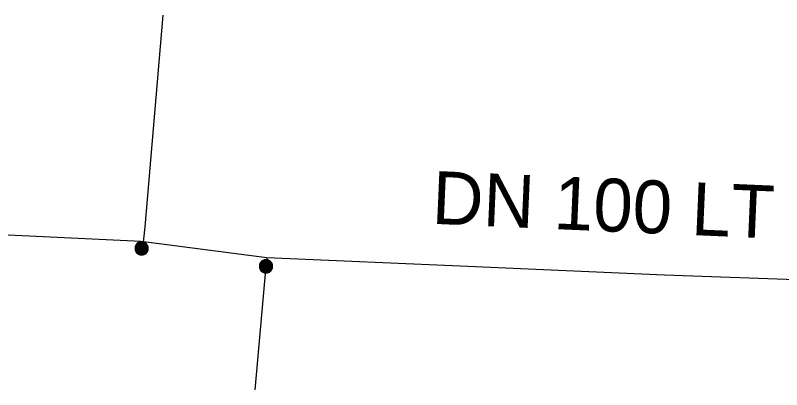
# Model space of a CAD drawing. Extents: x -832382 to -831581, y -1074670 to -1074251.
# Drawn here: x -831799.98 to -831771.02, y -1074605.05 to -1074590.89 of the extents above; entities that cross this region are included whole.
import ezdxf

# ---------------------------------------------------------------- set-up
doc = ezdxf.new("R2010")
doc.units = 0
for name, color, linetype in [('Přípojka vodovodu', 7, 'Continuous'), ('Přípojkový uzávěr', 7, 'Continuous'), ('Roz-řad', 7, 'Continuous'), ('Roz-řad-popis základní', 7, 'Continuous')]:
    doc.layers.add(name, color=color, linetype=linetype)

msp = doc.modelspace()

# ---------------------------------------------------------------- linework, layer by layer
at = {"layer": 'Přípojka vodovodu'}
for points in [[(-831795.23, -1074599.43), (-831795.21, -1074599.7), (-831795.19, -1074599.93), (-831795.08, -1074598.89), (-831794.395, -1074590.887)], [(-831790.48, -1074600.05), (-831790.51, -1074600.38), (-831790.934, -1074605.047)]]:
    msp.add_lwpolyline(points, dxfattribs=at)
at = {"layer": 'Přípojkový uzávěr'}
for points in [[(-831795.21, -1074599.45), (-831795.147, -1074599.45), (-831795.087, -1074599.482), (-831795.028, -1074599.514), (-831794.994, -1074599.575), (-831794.96, -1074599.635), (-831794.96, -1074599.7), (-831794.96, -1074599.765), (-831794.993, -1074599.825), (-831795.026, -1074599.884), (-831795.085, -1074599.917), (-831795.145, -1074599.95), (-831795.21, -1074599.95), (-831795.275, -1074599.95), (-831795.335, -1074599.917), (-831795.394, -1074599.884), (-831795.427, -1074599.825), (-831795.46, -1074599.765), (-831795.46, -1074599.7), (-831795.46, -1074599.635), (-831795.426, -1074599.575), (-831795.393, -1074599.514), (-831795.333, -1074599.482), (-831795.273, -1074599.45), (-831795.21, -1074599.45)], [(-831795.21, -1074599.473), (-831795.267, -1074599.473), (-831795.322, -1074599.503), (-831795.376, -1074599.532), (-831795.406, -1074599.586), (-831795.437, -1074599.641), (-831795.437, -1074599.7), (-831795.437, -1074599.759), (-831795.407, -1074599.813), (-831795.377, -1074599.867), (-831795.323, -1074599.897), (-831795.269, -1074599.927), (-831795.21, -1074599.927), (-831795.151, -1074599.927), (-831795.097, -1074599.897), (-831795.043, -1074599.867), (-831795.013, -1074599.813), (-831794.983, -1074599.759), (-831794.983, -1074599.7), (-831794.983, -1074599.641), (-831795.014, -1074599.586), (-831795.045, -1074599.532), (-831795.099, -1074599.503), (-831795.153, -1074599.473), (-831795.21, -1074599.473)], [(-831795.21, -1074599.491), (-831795.157, -1074599.491), (-831795.107, -1074599.518), (-831795.057, -1074599.544), (-831795.029, -1074599.595), (-831795.001, -1074599.645), (-831795.001, -1074599.7), (-831795.001, -1074599.755), (-831795.028, -1074599.804), (-831795.055, -1074599.854), (-831795.106, -1074599.882), (-831795.156, -1074599.909), (-831795.21, -1074599.909), (-831795.264, -1074599.909), (-831795.314, -1074599.882), (-831795.365, -1074599.854), (-831795.392, -1074599.804), (-831795.419, -1074599.755), (-831795.419, -1074599.7), (-831795.419, -1074599.645), (-831795.391, -1074599.595), (-831795.363, -1074599.544), (-831795.313, -1074599.518), (-831795.263, -1074599.491), (-831795.21, -1074599.491)], [(-831795.21, -1074599.512), (-831795.289, -1074599.512), (-831795.343, -1074599.567), (-831795.397, -1074599.622), (-831795.397, -1074599.7), (-831795.397, -1074599.778), (-831795.343, -1074599.833), (-831795.288, -1074599.887), (-831795.21, -1074599.887), (-831795.132, -1074599.887), (-831795.077, -1074599.833), (-831795.022, -1074599.778), (-831795.022, -1074599.7), (-831795.022, -1074599.622), (-831795.077, -1074599.567), (-831795.132, -1074599.512), (-831795.21, -1074599.512)], [(-831795.21, -1074599.535), (-831795.142, -1074599.535), (-831795.094, -1074599.583), (-831795.046, -1074599.631), (-831795.046, -1074599.7), (-831795.046, -1074599.768), (-831795.094, -1074599.816), (-831795.142, -1074599.864), (-831795.21, -1074599.864), (-831795.279, -1074599.864), (-831795.327, -1074599.816), (-831795.375, -1074599.768), (-831795.375, -1074599.7), (-831795.375, -1074599.631), (-831795.327, -1074599.583), (-831795.279, -1074599.535), (-831795.21, -1074599.535)], [(-831795.21, -1074599.555), (-831795.271, -1074599.555), (-831795.313, -1074599.597), (-831795.355, -1074599.64), (-831795.355, -1074599.7), (-831795.355, -1074599.759), (-831795.313, -1074599.802), (-831795.271, -1074599.844), (-831795.21, -1074599.844), (-831795.151, -1074599.844), (-831795.108, -1074599.802), (-831795.066, -1074599.759), (-831795.066, -1074599.7), (-831795.066, -1074599.64), (-831795.108, -1074599.597), (-831795.15, -1074599.555), (-831795.21, -1074599.555)], [(-831795.21, -1074599.575), (-831795.158, -1074599.575), (-831795.121, -1074599.612), (-831795.085, -1074599.648), (-831795.085, -1074599.7), (-831795.085, -1074599.752), (-831795.122, -1074599.789), (-831795.158, -1074599.825), (-831795.21, -1074599.825), (-831795.262, -1074599.825), (-831795.298, -1074599.789), (-831795.335, -1074599.752), (-831795.335, -1074599.7), (-831795.335, -1074599.648), (-831795.299, -1074599.612), (-831795.262, -1074599.575), (-831795.21, -1074599.575)], [(-831795.21, -1074599.598), (-831795.252, -1074599.598), (-831795.282, -1074599.628), (-831795.312, -1074599.658), (-831795.312, -1074599.7), (-831795.312, -1074599.742), (-831795.282, -1074599.772), (-831795.252, -1074599.801), (-831795.21, -1074599.801), (-831795.168, -1074599.801), (-831795.138, -1074599.772), (-831795.109, -1074599.742), (-831795.109, -1074599.7), (-831795.109, -1074599.658), (-831795.138, -1074599.628), (-831795.168, -1074599.598), (-831795.21, -1074599.598)], [(-831795.21, -1074599.616), (-831795.175, -1074599.616), (-831795.151, -1074599.64), (-831795.126, -1074599.665), (-831795.126, -1074599.7), (-831795.126, -1074599.735), (-831795.151, -1074599.759), (-831795.175, -1074599.784), (-831795.21, -1074599.784), (-831795.245, -1074599.784), (-831795.27, -1074599.759), (-831795.294, -1074599.735), (-831795.294, -1074599.7), (-831795.294, -1074599.665), (-831795.27, -1074599.64), (-831795.245, -1074599.616), (-831795.21, -1074599.616)], [(-831795.21, -1074599.637), (-831795.236, -1074599.637), (-831795.254, -1074599.656), (-831795.272, -1074599.674), (-831795.272, -1074599.7), (-831795.272, -1074599.726), (-831795.254, -1074599.744), (-831795.236, -1074599.762), (-831795.21, -1074599.762), (-831795.184, -1074599.762), (-831795.166, -1074599.744), (-831795.147, -1074599.726), (-831795.147, -1074599.7), (-831795.147, -1074599.674), (-831795.166, -1074599.656), (-831795.184, -1074599.637), (-831795.21, -1074599.637)], [(-831795.21, -1074599.661), (-831795.194, -1074599.661), (-831795.182, -1074599.672), (-831795.171, -1074599.683), (-831795.171, -1074599.7), (-831795.171, -1074599.716), (-831795.182, -1074599.728), (-831795.194, -1074599.739), (-831795.21, -1074599.739), (-831795.226, -1074599.739), (-831795.238, -1074599.728), (-831795.249, -1074599.716), (-831795.249, -1074599.7), (-831795.249, -1074599.683), (-831795.238, -1074599.672), (-831795.226, -1074599.661), (-831795.21, -1074599.661)], [(-831795.21, -1074599.677), (-831795.22, -1074599.677), (-831795.227, -1074599.683), (-831795.234, -1074599.69), (-831795.234, -1074599.7), (-831795.234, -1074599.71), (-831795.227, -1074599.717), (-831795.22, -1074599.723), (-831795.21, -1074599.723), (-831795.2, -1074599.723), (-831795.194, -1074599.717), (-831795.187, -1074599.71), (-831795.187, -1074599.7), (-831795.187, -1074599.69), (-831795.194, -1074599.683), (-831795.2, -1074599.677), (-831795.21, -1074599.677)], [(-831790.51, -1074600.13), (-831790.447, -1074600.13), (-831790.387, -1074600.162), (-831790.328, -1074600.194), (-831790.294, -1074600.255), (-831790.26, -1074600.315), (-831790.26, -1074600.38), (-831790.26, -1074600.445), (-831790.293, -1074600.505), (-831790.326, -1074600.564), (-831790.385, -1074600.597), (-831790.445, -1074600.63), (-831790.51, -1074600.63), (-831790.575, -1074600.63), (-831790.635, -1074600.597), (-831790.694, -1074600.564), (-831790.727, -1074600.505), (-831790.76, -1074600.445), (-831790.76, -1074600.38), (-831790.76, -1074600.315), (-831790.726, -1074600.255), (-831790.693, -1074600.194), (-831790.633, -1074600.162), (-831790.573, -1074600.13), (-831790.51, -1074600.13)], [(-831790.51, -1074600.153), (-831790.567, -1074600.153), (-831790.622, -1074600.183), (-831790.676, -1074600.212), (-831790.706, -1074600.266), (-831790.737, -1074600.321), (-831790.737, -1074600.38), (-831790.737, -1074600.439), (-831790.707, -1074600.493), (-831790.677, -1074600.547), (-831790.623, -1074600.577), (-831790.569, -1074600.607), (-831790.51, -1074600.607), (-831790.451, -1074600.607), (-831790.397, -1074600.577), (-831790.343, -1074600.547), (-831790.313, -1074600.493), (-831790.283, -1074600.439), (-831790.283, -1074600.38), (-831790.283, -1074600.321), (-831790.314, -1074600.266), (-831790.345, -1074600.212), (-831790.399, -1074600.183), (-831790.453, -1074600.153), (-831790.51, -1074600.153)], [(-831790.51, -1074600.171), (-831790.457, -1074600.171), (-831790.407, -1074600.198), (-831790.357, -1074600.224), (-831790.329, -1074600.275), (-831790.301, -1074600.325), (-831790.301, -1074600.38), (-831790.301, -1074600.435), (-831790.328, -1074600.484), (-831790.355, -1074600.534), (-831790.406, -1074600.562), (-831790.456, -1074600.589), (-831790.51, -1074600.589), (-831790.564, -1074600.589), (-831790.614, -1074600.562), (-831790.665, -1074600.534), (-831790.692, -1074600.484), (-831790.719, -1074600.435), (-831790.719, -1074600.38), (-831790.719, -1074600.325), (-831790.691, -1074600.275), (-831790.663, -1074600.224), (-831790.613, -1074600.198), (-831790.563, -1074600.171), (-831790.51, -1074600.171)], [(-831790.51, -1074600.193), (-831790.589, -1074600.193), (-831790.643, -1074600.247), (-831790.698, -1074600.302), (-831790.698, -1074600.38), (-831790.698, -1074600.458), (-831790.643, -1074600.513), (-831790.588, -1074600.568), (-831790.51, -1074600.568), (-831790.432, -1074600.568), (-831790.377, -1074600.513), (-831790.323, -1074600.458), (-831790.323, -1074600.38), (-831790.323, -1074600.302), (-831790.377, -1074600.247), (-831790.432, -1074600.193), (-831790.51, -1074600.193)], [(-831790.51, -1074600.215), (-831790.442, -1074600.215), (-831790.394, -1074600.263), (-831790.346, -1074600.311), (-831790.346, -1074600.38), (-831790.346, -1074600.448), (-831790.394, -1074600.496), (-831790.442, -1074600.544), (-831790.51, -1074600.544), (-831790.579, -1074600.544), (-831790.627, -1074600.496), (-831790.675, -1074600.448), (-831790.675, -1074600.38), (-831790.675, -1074600.311), (-831790.627, -1074600.263), (-831790.579, -1074600.215), (-831790.51, -1074600.215)], [(-831790.51, -1074600.235), (-831790.571, -1074600.235), (-831790.613, -1074600.277), (-831790.655, -1074600.32), (-831790.655, -1074600.38), (-831790.655, -1074600.439), (-831790.613, -1074600.482), (-831790.571, -1074600.524), (-831790.51, -1074600.524), (-831790.451, -1074600.524), (-831790.408, -1074600.482), (-831790.366, -1074600.439), (-831790.366, -1074600.38), (-831790.366, -1074600.32), (-831790.408, -1074600.277), (-831790.45, -1074600.235), (-831790.51, -1074600.235)], [(-831790.51, -1074600.255), (-831790.458, -1074600.255), (-831790.421, -1074600.292), (-831790.385, -1074600.328), (-831790.385, -1074600.38), (-831790.385, -1074600.432), (-831790.422, -1074600.469), (-831790.458, -1074600.505), (-831790.51, -1074600.505), (-831790.562, -1074600.505), (-831790.598, -1074600.469), (-831790.635, -1074600.432), (-831790.635, -1074600.38), (-831790.635, -1074600.328), (-831790.599, -1074600.292), (-831790.562, -1074600.255), (-831790.51, -1074600.255)], [(-831790.51, -1074600.278), (-831790.552, -1074600.278), (-831790.582, -1074600.308), (-831790.612, -1074600.338), (-831790.612, -1074600.38), (-831790.612, -1074600.422), (-831790.582, -1074600.452), (-831790.552, -1074600.481), (-831790.51, -1074600.481), (-831790.468, -1074600.481), (-831790.438, -1074600.452), (-831790.409, -1074600.422), (-831790.409, -1074600.38), (-831790.409, -1074600.338), (-831790.438, -1074600.308), (-831790.468, -1074600.278), (-831790.51, -1074600.278)], [(-831790.51, -1074600.296), (-831790.475, -1074600.296), (-831790.451, -1074600.32), (-831790.426, -1074600.345), (-831790.426, -1074600.38), (-831790.426, -1074600.415), (-831790.451, -1074600.439), (-831790.475, -1074600.464), (-831790.51, -1074600.464), (-831790.545, -1074600.464), (-831790.57, -1074600.439), (-831790.594, -1074600.415), (-831790.594, -1074600.38), (-831790.594, -1074600.345), (-831790.57, -1074600.32), (-831790.545, -1074600.296), (-831790.51, -1074600.296)], [(-831790.51, -1074600.318), (-831790.536, -1074600.318), (-831790.554, -1074600.336), (-831790.573, -1074600.354), (-831790.573, -1074600.38), (-831790.573, -1074600.406), (-831790.554, -1074600.424), (-831790.536, -1074600.443), (-831790.51, -1074600.443), (-831790.484, -1074600.443), (-831790.466, -1074600.424), (-831790.448, -1074600.406), (-831790.448, -1074600.38), (-831790.448, -1074600.354), (-831790.466, -1074600.336), (-831790.484, -1074600.318), (-831790.51, -1074600.318)], [(-831790.51, -1074600.341), (-831790.494, -1074600.341), (-831790.482, -1074600.352), (-831790.471, -1074600.363), (-831790.471, -1074600.38), (-831790.471, -1074600.396), (-831790.482, -1074600.408), (-831790.494, -1074600.419), (-831790.51, -1074600.419), (-831790.526, -1074600.419), (-831790.538, -1074600.408), (-831790.549, -1074600.396), (-831790.549, -1074600.38), (-831790.549, -1074600.363), (-831790.538, -1074600.352), (-831790.526, -1074600.341), (-831790.51, -1074600.341)], [(-831790.51, -1074600.357), (-831790.52, -1074600.357), (-831790.527, -1074600.363), (-831790.534, -1074600.37), (-831790.534, -1074600.38), (-831790.534, -1074600.39), (-831790.527, -1074600.397), (-831790.52, -1074600.403), (-831790.51, -1074600.403), (-831790.5, -1074600.403), (-831790.494, -1074600.397), (-831790.487, -1074600.39), (-831790.487, -1074600.38), (-831790.487, -1074600.37), (-831790.494, -1074600.363), (-831790.5, -1074600.357), (-831790.51, -1074600.357)]]:
    msp.add_open_spline(points, degree=3, dxfattribs=at)
at = {"layer": 'Roz-řad'}
msp.add_lwpolyline([(-831817.84, -1074596.82), (-831810.37, -1074598.08), (-831803.21, -1074599), (-831800.8, -1074599.17), (-831795.23, -1074599.43), (-831790.48, -1074600.05), (-831782.88, -1074600.38), (-831775.44, -1074600.7), (-831769.76, -1074600.91), (-831769.61, -1074600.92), (-831762.47, -1074600.53), (-831757.17, -1074600.19), (-831756.85, -1074600.14), (-831751.4, -1074599.35), (-831747.85, -1074598.92), (-831740.33, -1074598.09), (-831732.29, -1074596.92), (-831726.18, -1074596.07), (-831724.17, -1074595.71), (-831717.16, -1074594.32), (-831709.92, -1074593.1)], dxfattribs=at)

# ---------------------------------------------------------------- texts
at = {"layer": 'Roz-řad-popis základní'}
msp.add_text('DN 100 LT', height=2, rotation=357.5137, dxfattribs=at).set_placement((-831784.26, -1074598.77))

doc.saveas('drawing.dxf')
